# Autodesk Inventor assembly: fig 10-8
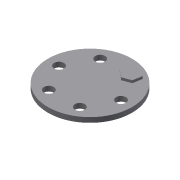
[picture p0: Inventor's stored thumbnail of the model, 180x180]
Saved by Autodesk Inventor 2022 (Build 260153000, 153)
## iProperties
Created: 2008-05
Part Number: fig 10-8
Document SubType Name: Assembly
Designer: CADCIM
Author: CADCIM
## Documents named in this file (3)
- D:\PROJECTS_2021\Resources\Part Files\c10_Inv_2021_prt\fig 10-8.iam
- D:\PROJECTS_2021\Resources\Part Files\c10_Inv_2021_prt\Part4.ipt
- D:\PROJECTS_2021\Resources\Part Files\c10_Inv_2021_prt\Part5.ipt
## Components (2 placed, 2 different names)
1. Part4:1 — Insert:1
2. Part5:1 — Insert:1
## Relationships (1: Insert 1)
- Insert:1: Part4:1 ↔ Part5:1
